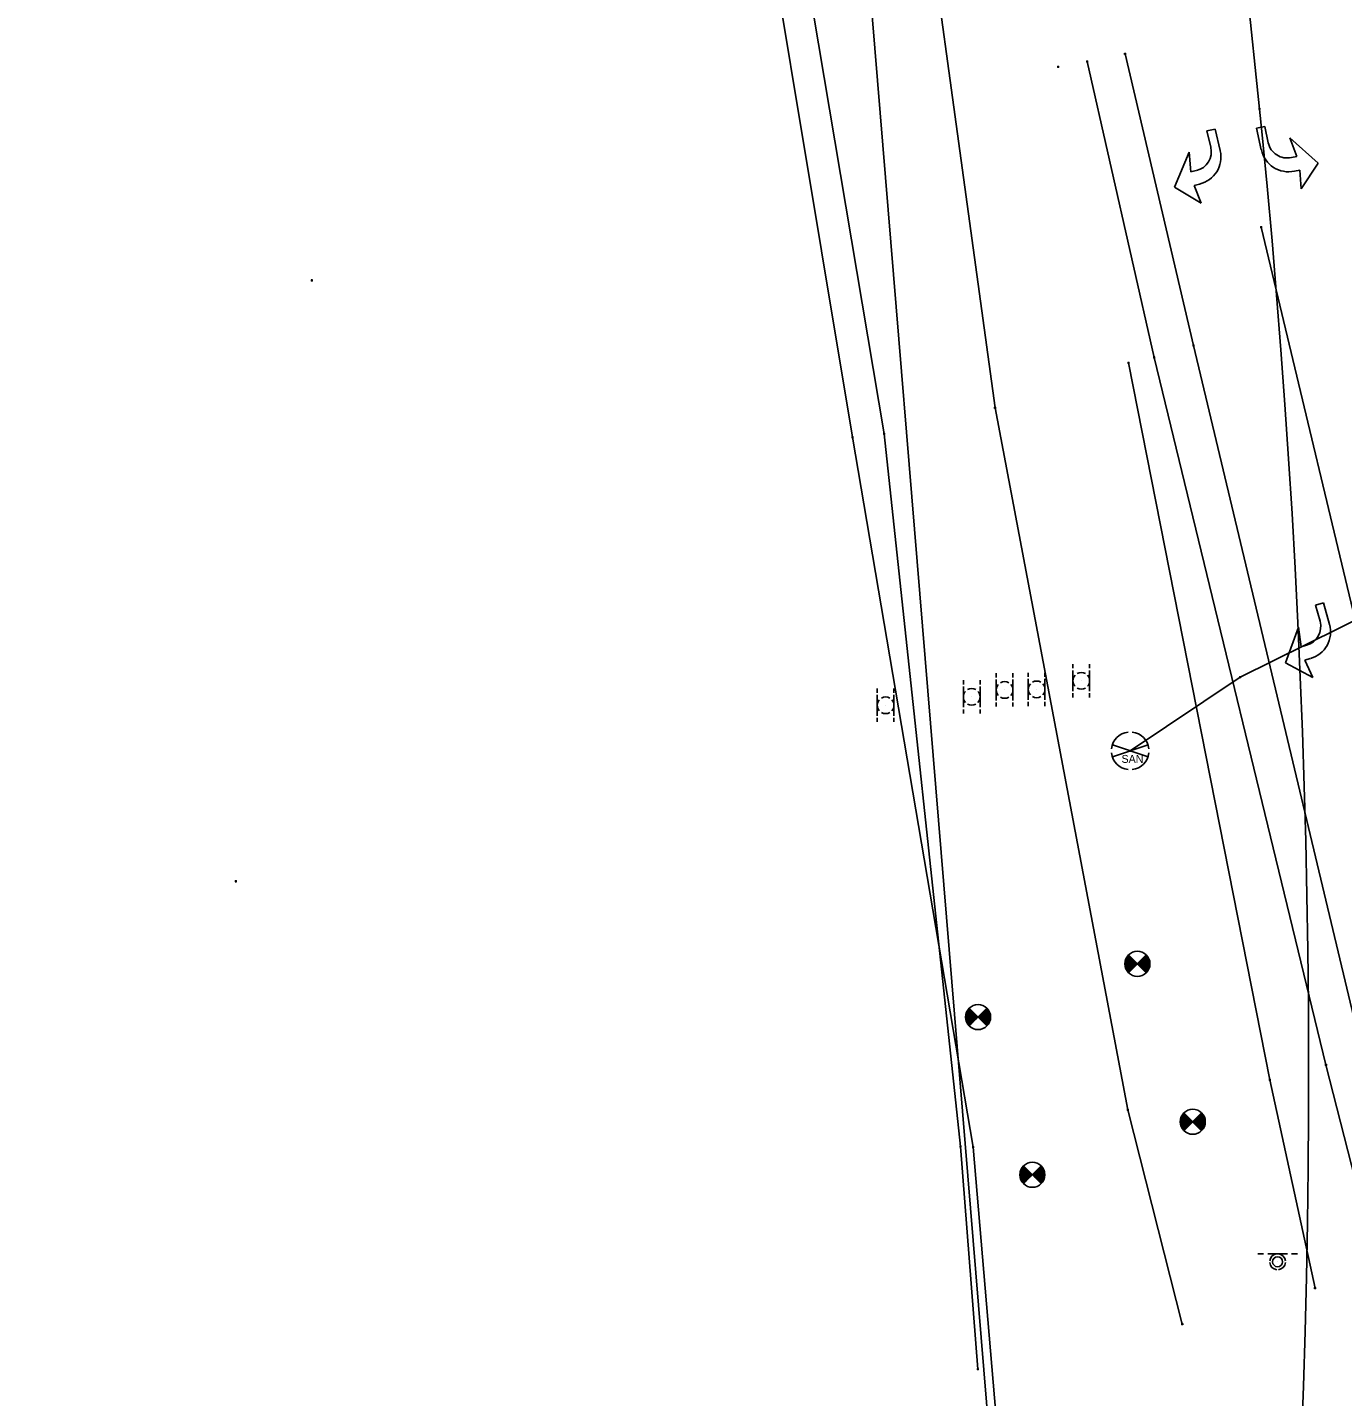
# Model space of a CAD drawing. Extents: x 1954856 to 2011933, y 399149 to 426294.
# Drawn here: x 2006095.1 to 2006252.8, y 401898.9 to 402063.1 of the extents above; entities that cross this region are included whole.
import ezdxf

# ---------------------------------------------------------------- set-up
doc = ezdxf.new("R2010")
doc.units = 0
for name, color, linetype in [('BankMent_ep', 7, 'Continuous'), ('BaselineSurvey', 7, 'Continuous'), ('Core_ep', 7, 'Continuous'), ('DelineatorPost_ep', 7, 'Continuous'), ('ElecAer_ep', 7, 'Continuous'), ('PavtAsphalt_ep', 7, 'Continuous'), ('PMRK_ep', 7, 'Continuous'), ('PMTAL_ep', 7, 'Continuous'), ('PMTAR_ep', 7, 'Continuous'), ('PointLocator_ep', 7, 'Continuous'), ('SanitaryFM_B_ep', 7, 'Continuous'), ('ShldrPaved_ep', 7, 'Continuous'), ('SignSingle_ep', 7, 'Continuous'), ('TreeLineWoods_ep', 7, 'Continuous'), ('ValveCvrSewer_ep', 7, 'Continuous')]:
    doc.layers.add(name, color=color, linetype=linetype)

msp = doc.modelspace()

# ---------------------------------------------------------------- linework, layer by layer
at = {"layer": 'BankMent_ep'}
for p, q in [((2006244.08, 401936.85), (2006227.1, 402022.84)), ((2006249.48, 401911.89), (2006244.08, 401936.85))]:
    msp.add_line(p, q, dxfattribs=at)
for points in [[(2006233.57, 401907.58), (2006227.04, 401933.28), (2006211.12, 402017.46), (2006199.01, 402105.59), (2006186.57, 402167.64), (2006181.34, 402190.18)], [(2006209.06, 401902.17), (2006206.97, 401928.86), (2006197.82, 402014.31), (2006182.77, 402103.86), (2006169.7, 402164.94), (2006165.83, 402187.63)]]:
    msp.add_lwpolyline(points, dxfattribs=at)
at = {"layer": 'BaselineSurvey'}
msp.add_arc((2005102.8, 401937.33), 1145.91, 329.99111, 11.93882, dxfattribs=at)
msp.add_arc((2005102.8, 401937.33), 1145.91, 329.99111, 11.93882, dxfattribs=at)
at = {"layer": 'Core_ep'}
for p, q in [((2006226.82, 401951.39), (2006226.82, 401950.15)), ((2006226.9, 401951.54), (2006226.9, 401950)), ((2006226.97, 401951.65), (2006226.97, 401949.89)), ((2006227.05, 401951.74), (2006227.05, 401949.79)), ((2006227.12, 401951.83), (2006227.12, 401949.71)), ((2006229.25, 401951.83), (2006227.13, 401949.71)), ((2006227.13, 401951.83), (2006229.25, 401949.71)), ((2006227.2, 401951.76), (2006227.2, 401949.78)), ((2006227.27, 401951.68), (2006227.27, 401949.85)), ((2006227.35, 401951.61), (2006227.35, 401949.93)), ((2006227.42, 401951.53), (2006227.42, 401950)), ((2006227.5, 401951.46), (2006227.5, 401950.08)), ((2006227.5, 401951.46), (2006227.5, 401950.16)), ((2006227.57, 401951.38), (2006227.57, 401950.16)), ((2006227.65, 401951.31), (2006227.65, 401950.23)), ((2006228.73, 401951.31), (2006228.73, 401950.23)), ((2006228.8, 401951.38), (2006228.8, 401950.16)), ((2006228.88, 401951.46), (2006228.88, 401950.08)), ((2006228.95, 401951.53), (2006228.95, 401950)), ((2006229.03, 401951.61), (2006229.03, 401949.93)), ((2006229.1, 401951.68), (2006229.1, 401949.85)), ((2006229.18, 401951.76), (2006229.18, 401949.78)), ((2006229.25, 401951.83), (2006229.25, 401949.71)), ((2006229.33, 401951.74), (2006229.33, 401949.79)), ((2006229.4, 401951.65), (2006229.4, 401949.89)), ((2006229.48, 401951.54), (2006229.48, 401950)), ((2006229.55, 401951.39), (2006229.55, 401950.15)), ((2006226.75, 401951.19), (2006226.75, 401950.35)), ((2006227.73, 401951.23), (2006227.73, 401950.31)), ((2006227.8, 401951.16), (2006227.8, 401950.38)), ((2006227.88, 401951.08), (2006227.88, 401950.46)), ((2006227.95, 401951.01), (2006227.95, 401950.53)), ((2006228.03, 401950.93), (2006228.03, 401950.61)), ((2006228.1, 401950.86), (2006228.1, 401950.68)), ((2006228.19, 401950.77), (2006228.19, 401950.77)), ((2006228.27, 401950.86), (2006228.27, 401950.68)), ((2006228.35, 401950.93), (2006228.35, 401950.61)), ((2006228.42, 401951.01), (2006228.42, 401950.53)), ((2006228.5, 401951.08), (2006228.5, 401950.46)), ((2006228.57, 401951.16), (2006228.57, 401950.38)), ((2006228.65, 401951.23), (2006228.65, 401950.31)), ((2006229.63, 401951.19), (2006229.63, 401950.35)), ((2006207.65, 401944.8), (2006207.65, 401943.96)), ((2006207.72, 401945), (2006207.72, 401943.77)), ((2006207.8, 401945.15), (2006207.8, 401943.62)), ((2006207.87, 401945.26), (2006207.87, 401943.5)), ((2006207.95, 401945.36), (2006207.95, 401943.41)), ((2006208.02, 401945.44), (2006208.02, 401943.33)), ((2006210.15, 401945.44), (2006208.03, 401943.32)), ((2006208.03, 401945.44), (2006210.15, 401943.32)), ((2006208.1, 401945.37), (2006208.1, 401943.39)), ((2006208.17, 401945.3), (2006208.17, 401943.47)), ((2006208.25, 401945.22), (2006208.25, 401943.54)), ((2006208.32, 401945.15), (2006208.32, 401943.62)), ((2006208.4, 401945.07), (2006208.4, 401943.69)), ((2006208.4, 401945.07), (2006208.4, 401943.77)), ((2006208.47, 401945), (2006208.47, 401943.77)), ((2006208.55, 401944.92), (2006208.55, 401943.84)), ((2006208.63, 401944.84), (2006208.63, 401943.92)), ((2006208.7, 401944.77), (2006208.7, 401944)), ((2006209.47, 401944.77), (2006209.47, 401944)), ((2006209.55, 401944.84), (2006209.55, 401943.92)), ((2006209.63, 401944.92), (2006209.63, 401943.84)), ((2006209.7, 401945), (2006209.7, 401943.77)), ((2006209.78, 401945.07), (2006209.78, 401943.69)), ((2006209.85, 401945.15), (2006209.85, 401943.62)), ((2006209.93, 401945.22), (2006209.93, 401943.54)), ((2006210, 401945.3), (2006210, 401943.47)), ((2006210.08, 401945.37), (2006210.08, 401943.39)), ((2006210.15, 401945.44), (2006210.15, 401943.33)), ((2006210.23, 401945.36), (2006210.23, 401943.41)), ((2006210.3, 401945.26), (2006210.3, 401943.5)), ((2006210.38, 401945.15), (2006210.38, 401943.62)), ((2006210.45, 401945), (2006210.45, 401943.76)), ((2006210.53, 401944.8), (2006210.53, 401943.96)), ((2006208.78, 401944.69), (2006208.78, 401944.07)), ((2006208.85, 401944.62), (2006208.85, 401944.15)), ((2006208.93, 401944.54), (2006208.93, 401944.22)), ((2006209, 401944.47), (2006209, 401944.3)), ((2006209.09, 401944.38), (2006209.09, 401944.38)), ((2006209.17, 401944.47), (2006209.17, 401944.3)), ((2006209.25, 401944.54), (2006209.25, 401944.22)), ((2006209.32, 401944.62), (2006209.32, 401944.15)), ((2006209.4, 401944.69), (2006209.4, 401944.07)), ((2006233.39, 401932.25), (2006233.39, 401931.41)), ((2006233.46, 401932.44), (2006233.46, 401931.21)), ((2006233.54, 401932.59), (2006233.54, 401931.06)), ((2006233.62, 401932.7), (2006233.62, 401930.95)), ((2006233.69, 401932.8), (2006233.69, 401930.85)), ((2006235.89, 401932.89), (2006233.77, 401930.76)), ((2006233.77, 401932.89), (2006235.89, 401930.76)), ((2006233.77, 401932.88), (2006233.77, 401930.77)), ((2006233.84, 401932.82), (2006233.84, 401930.84)), ((2006233.92, 401932.74), (2006233.92, 401930.91)), ((2006233.99, 401932.67), (2006233.99, 401930.99)), ((2006234.07, 401932.59), (2006234.07, 401931.06)), ((2006234.14, 401932.52), (2006234.14, 401931.14)), ((2006234.14, 401932.52), (2006234.14, 401931.21)), ((2006234.22, 401932.44), (2006234.22, 401931.21)), ((2006234.29, 401932.37), (2006234.29, 401931.29)), ((2006234.37, 401932.29), (2006234.37, 401931.36)), ((2006234.44, 401932.21), (2006234.44, 401931.44)), ((2006234.52, 401932.14), (2006234.52, 401931.51)), ((2006234.59, 401932.06), (2006234.59, 401931.59)), ((2006234.67, 401931.99), (2006234.67, 401931.66)), ((2006234.74, 401931.91), (2006234.74, 401931.74)), ((2006234.83, 401931.83), (2006234.83, 401931.83)), ((2006234.92, 401931.91), (2006234.92, 401931.74)), ((2006234.99, 401931.99), (2006234.99, 401931.66)), ((2006235.07, 401932.06), (2006235.07, 401931.59)), ((2006235.14, 401932.14), (2006235.14, 401931.51)), ((2006235.22, 401932.21), (2006235.22, 401931.44)), ((2006235.29, 401932.29), (2006235.29, 401931.36)), ((2006235.37, 401932.37), (2006235.37, 401931.29)), ((2006235.44, 401932.44), (2006235.44, 401931.21)), ((2006235.52, 401932.52), (2006235.52, 401931.14)), ((2006235.6, 401932.59), (2006235.6, 401931.06)), ((2006235.67, 401932.67), (2006235.67, 401930.99)), ((2006235.75, 401932.74), (2006235.75, 401930.91)), ((2006235.82, 401932.82), (2006235.82, 401930.84)), ((2006235.9, 401932.88), (2006235.9, 401930.77)), ((2006235.97, 401932.8), (2006235.97, 401930.85)), ((2006236.05, 401932.7), (2006236.05, 401930.95)), ((2006236.12, 401932.59), (2006236.12, 401931.06)), ((2006236.2, 401932.45), (2006236.2, 401931.2)), ((2006236.27, 401932.25), (2006236.27, 401931.41)), ((2006214.15, 401925.89), (2006214.15, 401925.05)), ((2006214.22, 401926.09), (2006214.22, 401924.86)), ((2006214.3, 401926.24), (2006214.3, 401924.71)), ((2006214.38, 401926.35), (2006214.38, 401924.59)), ((2006214.45, 401926.45), (2006214.45, 401924.5)), ((2006216.65, 401926.53), (2006214.53, 401924.41)), ((2006214.53, 401926.53), (2006216.65, 401924.41)), ((2006214.53, 401926.53), (2006214.53, 401924.42)), ((2006214.6, 401926.46), (2006214.6, 401924.48)), ((2006214.68, 401926.39), (2006214.68, 401924.56)), ((2006214.75, 401926.31), (2006214.75, 401924.63)), ((2006214.83, 401926.24), (2006214.83, 401924.71)), ((2006214.9, 401926.16), (2006214.9, 401924.78)), ((2006214.9, 401926.16), (2006214.9, 401924.86)), ((2006214.98, 401926.09), (2006214.98, 401924.86)), ((2006215.05, 401926.01), (2006215.05, 401924.93)), ((2006215.13, 401925.94), (2006215.13, 401925.01)), ((2006215.2, 401925.86), (2006215.2, 401925.09)), ((2006215.28, 401925.79), (2006215.28, 401925.16)), ((2006215.35, 401925.71), (2006215.35, 401925.24)), ((2006215.43, 401925.64), (2006215.43, 401925.31)), ((2006215.5, 401925.56), (2006215.5, 401925.39)), ((2006215.59, 401925.47), (2006215.59, 401925.47)), ((2006215.68, 401925.56), (2006215.68, 401925.39)), ((2006215.75, 401925.64), (2006215.75, 401925.31)), ((2006215.83, 401925.71), (2006215.83, 401925.24)), ((2006215.9, 401925.79), (2006215.9, 401925.16)), ((2006215.98, 401925.86), (2006215.98, 401925.09)), ((2006216.05, 401925.94), (2006216.05, 401925.01)), ((2006216.13, 401926.01), (2006216.13, 401924.93)), ((2006216.2, 401926.09), (2006216.2, 401924.86)), ((2006216.28, 401926.16), (2006216.28, 401924.78)), ((2006216.36, 401926.24), (2006216.36, 401924.71)), ((2006216.43, 401926.31), (2006216.43, 401924.63)), ((2006216.51, 401926.39), (2006216.51, 401924.56)), ((2006216.58, 401926.46), (2006216.58, 401924.48)), ((2006216.66, 401926.53), (2006216.66, 401924.42)), ((2006216.73, 401926.45), (2006216.73, 401924.5)), ((2006216.81, 401926.35), (2006216.81, 401924.59)), ((2006216.88, 401926.24), (2006216.88, 401924.71)), ((2006216.96, 401926.1), (2006216.96, 401924.85)), ((2006217.03, 401925.89), (2006217.03, 401925.05))]:
    msp.add_line(p, q, dxfattribs=at)
for centre in [(2006228.19, 401950.77), (2006209.09, 401944.38), (2006234.83, 401931.83), (2006215.59, 401925.47)]:
    msp.add_circle(centre, 1.5, dxfattribs=at)
at = {"layer": 'DelineatorPost_ep'}
for p, q in [((2006220.46, 401986.71), (2006220.46, 401986.21)), ((2006220.46, 401983.46), (2006220.46, 401985.96)), ((2006222.46, 401986.71), (2006222.46, 401986.21)), ((2006222.46, 401985.96), (2006222.46, 401983.46)), ((2006207.32, 401984.78), (2006207.32, 401984.28)), ((2006209.32, 401984.78), (2006209.32, 401984.28)), ((2006211.26, 401985.61), (2006211.26, 401985.11)), ((2006211.26, 401982.36), (2006211.26, 401984.86)), ((2006213.26, 401985.61), (2006213.26, 401985.11)), ((2006213.26, 401984.86), (2006213.26, 401982.36)), ((2006215.1, 401985.68), (2006215.1, 401985.18)), ((2006215.1, 401982.43), (2006215.1, 401984.93)), ((2006217.1, 401985.68), (2006217.1, 401985.18)), ((2006217.1, 401984.93), (2006217.1, 401982.43)), ((2006221.46, 401984.71), (2006221.46, 401984.71)), ((2006196.99, 401983.77), (2006196.99, 401983.27)), ((2006196.99, 401980.52), (2006196.99, 401983.02)), ((2006198.99, 401983.77), (2006198.99, 401983.27)), ((2006198.99, 401983.02), (2006198.99, 401980.52)), ((2006207.32, 401981.53), (2006207.32, 401984.03)), ((2006208.32, 401982.78), (2006208.32, 401982.78)), ((2006209.32, 401984.03), (2006209.32, 401981.53)), ((2006212.26, 401983.61), (2006212.26, 401983.61)), ((2006216.1, 401983.68), (2006216.1, 401983.68)), ((2006220.46, 401983.21), (2006220.46, 401982.71)), ((2006222.46, 401983.21), (2006222.46, 401982.71)), ((2006197.99, 401981.77), (2006197.99, 401981.77)), ((2006207.32, 401981.28), (2006207.32, 401980.78)), ((2006209.32, 401981.28), (2006209.32, 401980.78)), ((2006211.26, 401982.11), (2006211.26, 401981.61)), ((2006213.26, 401982.11), (2006213.26, 401981.61)), ((2006215.1, 401982.18), (2006215.1, 401981.68)), ((2006217.1, 401982.18), (2006217.1, 401981.68)), ((2006196.99, 401980.27), (2006196.99, 401979.77)), ((2006198.99, 401980.27), (2006198.99, 401979.77))]:
    msp.add_line(p, q, dxfattribs=at)
for centre, start, end in [((2006212.26, 401983.61), 138.5904, 221.4096), ((2006212.26, 401983.61), 60, 120), ((2006212.26, 401983.61), 318.5904, 41.4096), ((2006216.1, 401983.68), 138.5904, 221.4096), ((2006216.1, 401983.68), 60, 120), ((2006216.1, 401983.68), 318.5904, 41.4096), ((2006221.46, 401984.71), 138.5904, 221.4096), ((2006221.46, 401984.71), 60, 120), ((2006221.46, 401984.71), 318.5904, 41.4096), ((2006197.99, 401981.77), 60, 120), ((2006208.32, 401982.78), 138.5904, 221.4096), ((2006208.32, 401982.78), 60, 120), ((2006208.32, 401982.78), 318.5904, 41.4096), ((2006212.26, 401983.61), 240, 300), ((2006216.1, 401983.68), 240, 300), ((2006221.46, 401984.71), 240, 300), ((2006197.99, 401981.77), 138.5904, 221.4096), ((2006197.99, 401981.77), 240, 300), ((2006197.99, 401981.77), 318.5904, 41.4096), ((2006208.32, 401982.78), 240, 300)]:
    msp.add_arc(centre, 1, start, end, dxfattribs=at)
at = {"layer": 'ElecAer_ep'}
msp.add_lwpolyline([(2006211.07, 401886.57), (2006189.36, 402149.77)], dxfattribs=at)
at = {"layer": 'PavtAsphalt_ep'}
for p, q in [((2006234.93, 402024.91), (2006226.7, 402059.89)), ((2006255.19, 401939.97), (2006234.93, 402024.91))]:
    msp.add_line(p, q, dxfattribs=at)
at = {"layer": 'PMRK_ep'}
msp.add_line((2006243.02, 402039.1), (2006266.21, 401942.09), dxfattribs=at)
at = {"layer": 'PMTAL_ep'}
for p, q in [((2006243.45, 402051.18), (2006242.47, 402050.97)), ((2006242.47, 402050.97), (2006243.04, 402048.36)), ((2006243.87, 402049.23), (2006243.45, 402051.18)), ((2006249.87, 402046.79), (2006246.48, 402049.8)), ((2006246.48, 402049.8), (2006247.31, 402047.59)), ((2006247.31, 402047.59), (2006246.65, 402047.45)), ((2006247.82, 402043.69), (2006249.87, 402046.79)), ((2006249.87, 402046.79), (2006249.87, 402046.79)), ((2006247.01, 402045.82), (2006247.66, 402045.96)), ((2006247.66, 402045.96), (2006247.82, 402043.69))]:
    msp.add_line(p, q, dxfattribs=at)
for centre, radius in [((2006246.3, 402049.08), 3.33), ((2006246.15, 402049.73), 2.33)]:
    msp.add_arc(centre, radius, 192.3763, 282.3763, dxfattribs=at)
at = {"layer": 'PMTAR_ep'}
for p, q in [((2006236.53, 402050.64), (2006237.5, 402050.87)), ((2006236.99, 402048.7), (2006236.53, 402050.64)), ((2006237.5, 402050.87), (2006238.11, 402048.28)), ((2006232.64, 402043.9), (2006234.39, 402048.08)), ((2006234.39, 402048.08), (2006234.6, 402045.74)), ((2006234.6, 402045.74), (2006235.25, 402045.89)), ((2006235.83, 402042), (2006232.64, 402043.9)), ((2006232.64, 402043.9), (2006232.64, 402043.9)), ((2006235.64, 402044.27), (2006234.99, 402044.11)), ((2006234.99, 402044.11), (2006235.83, 402042)), ((2006249.54, 401993.78), (2006250.5, 401994.05)), ((2006250.5, 401994.05), (2006251.23, 401991.48)), ((2006250.08, 401991.85), (2006249.54, 401993.78)), ((2006245.94, 401986.88), (2006247.52, 401991.13)), ((2006247.52, 401991.13), (2006247.83, 401988.79)), ((2006247.83, 401988.79), (2006248.47, 401988.97)), ((2006249.21, 401985.11), (2006245.94, 401986.88)), ((2006245.94, 401986.88), (2006245.94, 401986.88)), ((2006248.92, 401987.37), (2006248.28, 401987.19)), ((2006248.28, 401987.19), (2006249.21, 401985.11))]:
    msp.add_line(p, q, dxfattribs=at)
for centre, radius, start, end in [((2006234.72, 402048.16), 2.33, 283.3097, 13.3097), ((2006234.87, 402047.51), 3.33, 283.3097, 13.3097), ((2006247.84, 401991.22), 2.33, 285.7288, 15.7288), ((2006248.02, 401990.58), 3.33, 285.7288, 15.7288)]:
    msp.add_arc(centre, radius, start, end, dxfattribs=at)
at = {"layer": 'PointLocator_ep'}
for p, q in [((2006226.82, 402059.89), (2006226.57, 402059.89)), ((2006226.7, 402059.77), (2006226.7, 402060.02)), ((2006226.7, 402059.89), (2006226.7, 402059.89)), ((2006218.8, 402058.35), (2006218.55, 402058.35)), ((2006218.67, 402058.22), (2006218.67, 402058.47)), ((2006218.67, 402058.35), (2006218.67, 402058.35)), ((2006222.3, 402058.98), (2006222.05, 402058.98)), ((2006222.18, 402058.85), (2006222.18, 402059.1)), ((2006222.18, 402058.98), (2006222.18, 402058.98)), ((2006242.95, 402053.28), (2006242.7, 402053.28)), ((2006242.83, 402053.16), (2006242.83, 402053.41)), ((2006242.83, 402053.28), (2006242.83, 402053.28)), ((2006243.15, 402039.1), (2006242.9, 402039.1)), ((2006243.02, 402038.97), (2006243.02, 402039.22)), ((2006243.02, 402039.1), (2006243.02, 402039.1)), ((2006129.34, 402032.73), (2006129.09, 402032.73)), ((2006129.22, 402032.61), (2006129.22, 402032.86)), ((2006129.22, 402032.73), (2006129.22, 402032.73)), ((2006230.18, 402023.37), (2006230.18, 402023.62)), ((2006235.05, 402024.91), (2006234.8, 402024.91)), ((2006234.93, 402024.78), (2006234.93, 402025.03)), ((2006234.93, 402024.91), (2006234.93, 402024.91)), ((2006227.23, 402022.84), (2006226.98, 402022.84)), ((2006227.1, 402022.71), (2006227.1, 402022.96)), ((2006227.1, 402022.84), (2006227.1, 402022.84)), ((2006230.31, 402023.49), (2006230.06, 402023.49)), ((2006230.18, 402023.49), (2006230.18, 402023.49)), ((2006211.24, 402017.46), (2006210.99, 402017.46)), ((2006211.12, 402017.34), (2006211.12, 402017.59)), ((2006211.12, 402017.46), (2006211.12, 402017.46)), ((2006194.14, 402013.91), (2006193.89, 402013.91)), ((2006194.02, 402013.78), (2006194.02, 402014.03)), ((2006194.02, 402013.91), (2006194.02, 402013.91)), ((2006197.95, 402014.31), (2006197.7, 402014.31)), ((2006197.82, 402014.18), (2006197.82, 402014.43)), ((2006197.82, 402014.31), (2006197.82, 402014.31)), ((2006240.64, 401985.14), (2006240.39, 401985.14)), ((2006240.51, 401985.01), (2006240.51, 401985.26)), ((2006240.51, 401985.14), (2006240.51, 401985.14)), ((2006227.44, 401976.32), (2006227.19, 401976.32)), ((2006227.32, 401976.2), (2006227.32, 401976.45)), ((2006227.32, 401976.32), (2006227.32, 401976.32)), ((2006120.21, 401960.67), (2006119.96, 401960.67)), ((2006120.09, 401960.54), (2006120.09, 401960.79)), ((2006120.09, 401960.67), (2006120.09, 401960.67)), ((2006250.92, 401938.64), (2006250.67, 401938.64)), ((2006250.79, 401938.52), (2006250.79, 401938.77)), ((2006250.79, 401938.64), (2006250.79, 401938.64)), ((2006244.2, 401936.85), (2006243.95, 401936.85)), ((2006244.08, 401936.72), (2006244.08, 401936.97)), ((2006244.08, 401936.85), (2006244.08, 401936.85)), ((2006227.17, 401933.28), (2006226.92, 401933.28)), ((2006227.04, 401933.15), (2006227.04, 401933.4)), ((2006227.04, 401933.28), (2006227.04, 401933.28)), ((2006207.09, 401928.86), (2006206.84, 401928.86)), ((2006206.97, 401928.74), (2006206.97, 401928.99)), ((2006206.97, 401928.86), (2006206.97, 401928.86)), ((2006208.62, 401928.77), (2006208.37, 401928.77)), ((2006208.49, 401928.64), (2006208.49, 401928.89)), ((2006208.49, 401928.77), (2006208.49, 401928.77)), ((2006249.48, 401911.76), (2006249.48, 401912.01)), ((2006249.61, 401911.89), (2006249.36, 401911.89)), ((2006249.48, 401911.89), (2006249.48, 401911.89)), ((2006233.7, 401907.58), (2006233.45, 401907.58)), ((2006233.57, 401907.46), (2006233.57, 401907.71)), ((2006233.57, 401907.58), (2006233.57, 401907.58)), ((2006209.18, 401902.17), (2006208.93, 401902.17)), ((2006209.06, 401902.04), (2006209.06, 401902.29)), ((2006209.06, 401902.17), (2006209.06, 401902.17))]:
    msp.add_line(p, q, dxfattribs=at)
at = {"layer": 'SanitaryFM_B_ep'}
msp.add_lwpolyline([(2007401.95, 403818.63), (2007312.3, 403645.73), (2007290.75, 403604.1), (2007263.4, 403556.68), (2007243.69, 403523.41), (2007211.46, 403477.24), (2007146.71, 403360.43), (2007074.94, 403233.14), (2007057.11, 403197.22), (2007018.41, 403142.13), (2006986.05, 403110.09), (2006967.4, 403089.86), (2006949.18, 403062), (2006912.39, 403001.77), (2006860.92, 402920.48), (2006691.88, 402620.5), (2006600.9, 402464.44), (2006520.64, 402315.09), (2006403, 402102.49), (2006392.62, 402085.16), (2006366.88, 402033.22), (2006268.08, 401998.8), (2006240.51, 401985.14), (2006227.32, 401976.32)], dxfattribs=at)
at = {"layer": 'ShldrPaved_ep'}
for p, q in [((2006230.18, 402023.49), (2006222.18, 402058.98)), ((2006250.79, 401938.64), (2006230.18, 402023.49)), ((2006260.6, 401900.1), (2006250.79, 401938.64))]:
    msp.add_line(p, q, dxfattribs=at)
at = {"layer": 'SignSingle_ep'}
for p, q in [((2006242.62, 401915.99), (2006243.32, 401915.99)), ((2006243.82, 401915.99), (2006246.17, 401915.99)), ((2006246.67, 401915.99), (2006247.37, 401915.99)), ((2006244.99, 401915.04), (2006244.99, 401915.04))]:
    msp.add_line(p, q, dxfattribs=at)
msp.add_circle((2006244.99, 401915.04), 0.594, dxfattribs=at)
for start, end in [(96.0423, 173.9577), (6.0423, 83.9577), (186.0423, 263.9577), (276.0423, 353.9577)]:
    msp.add_arc((2006244.99, 401915.04), 0.95, start, end, dxfattribs=at)
at = {"layer": 'TreeLineWoods_ep'}
msp.add_lwpolyline([(2006207.12, 401803.9), (2006213.62, 401868.67), (2006208.49, 401928.77), (2006194.02, 402013.91), (2006179.22, 402103.09), (2006168.44, 402164.84), (2006163.63, 402187.19)], dxfattribs=at)
at = {"layer": 'ValveCvrSewer_ep'}
for p, q in [((2006225.19, 401975.6), (2006229.46, 401977.02)), ((2006229.46, 401975.6), (2006225.19, 401977.02)), ((2006227.32, 401976.31), (2006227.32, 401976.31))]:
    msp.add_line(p, q, dxfattribs=at)
for start, end in [(96.3794, 173.6206), (6.3794, 83.6206), (186.3794, 263.6206), (276.3794, 353.6206)]:
    msp.add_arc((2006227.32, 401976.31), 2.25, start, end, dxfattribs=at)

# ---------------------------------------------------------------- texts
msp.add_text('SAN', height=0.95, dxfattribs=at).set_placement((2006226.29, 401974.87))

doc.saveas('drawing.dxf')
